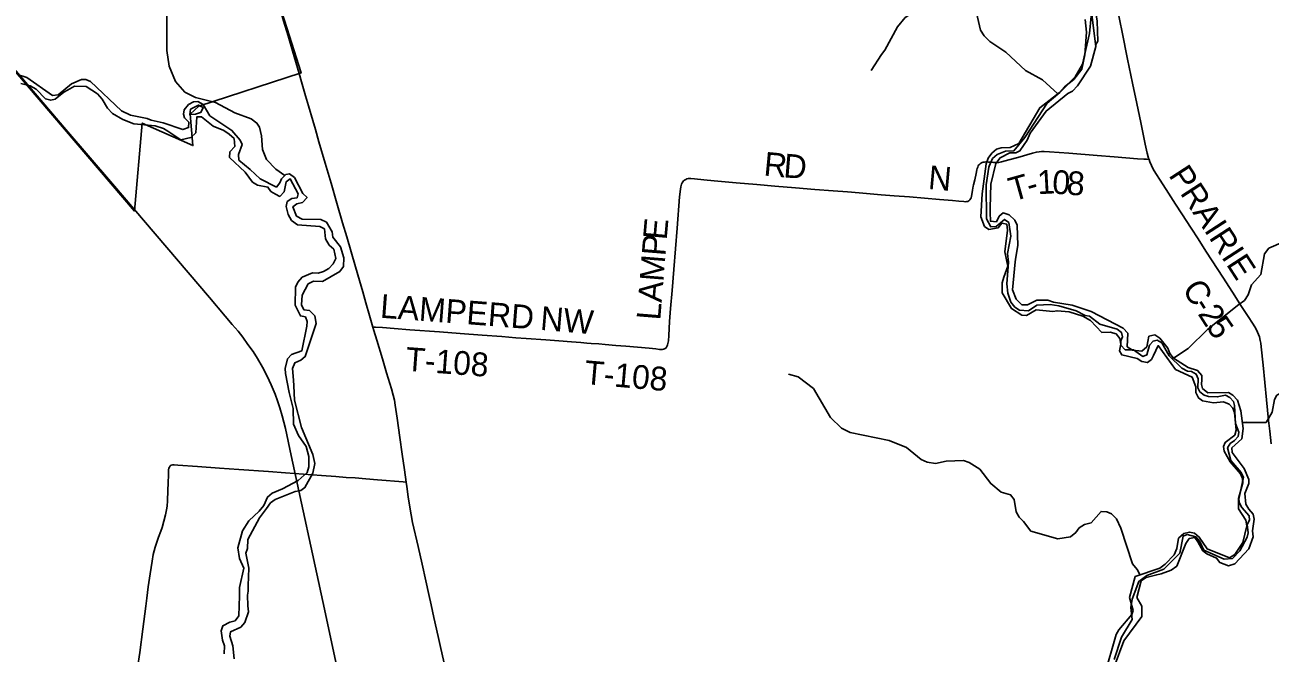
# Model space of a CAD drawing. Extents: x -51392 to 1635000, y 156707 to 696232.
# Drawn here: x 108334 to 124053, y 518358 to 526284 of the extents above; entities that cross this region are included whole.
import ezdxf

# ---------------------------------------------------------------- set-up
doc = ezdxf.new("R2010")
doc.units = 0
for name, color, linetype in [('GM_X_Corporation', 7, 'Continuous'), ('GM_X_County_Road', 7, 'Continuous'), ('GM_X_County_Road_Text', 7, 'Continuous'), ('GM_X_Major_River', 7, 'Continuous'), ('GM_X_Minor_River', 7, 'Continuous'), ('GM_X_Rail_Line', 7, 'Continuous'), ('GM_X_State_Route', 7, 'Continuous'), ('GM_X_Township', 7, 'Continuous'), ('GM_X_Township_Road', 7, 'Continuous'), ('GM_X_Township_Road_Text', 7, 'Continuous')]:
    doc.layers.add(name, color=color, linetype=linetype)

msp = doc.modelspace()

# ---------------------------------------------------------------- linework, layer by layer
at = {"layer": 'GM_X_Corporation'}
msp.add_lwpolyline([(111459, 526819), (111820, 525679), (110531, 525259), (110418, 525160), (110454, 524762), (109814, 525045), (109718, 523935), (107626, 526376)], dxfattribs=at)
at = {"layer": 'GM_X_County_Road'}
for points in [[(122525, 524588), (122520, 524603), (122502, 524666), (122476, 524778), (122420, 525051), (122370, 525292), (122317, 525549), (122253, 525854), (122185, 526192), (122156, 526337), (122110, 526561), (122091, 526658), (122068, 526770), (122045, 526883), (122009, 527060), (121987, 527155), (121961, 527250), (121922, 527375), (121848, 527610), (121792, 527781), (121760, 527874), (121738, 527924)], [(124067, 520997), (124049, 521160), (124035, 521291), (124009, 521552), (123964, 521992), (123942, 522221), (123936, 522270), (123930, 522302), (123919, 522349), (123908, 522379), (123895, 522409), (123872, 522452), (123838, 522508), (123767, 522618), (123686, 522742), (123607, 522866), (123464, 523087), (123242, 523431), (123145, 523583), (123055, 523721), (122940, 523900), (122860, 524023), (122771, 524161), (122664, 524326), (122611, 524409), (122577, 524466), (122555, 524510), (122536, 524556), (122525, 524588)], [(109757, 518171), (109785, 518365), (109823, 518658), (109860, 518951), (109872, 519049), (109891, 519195), (109914, 519357), (109926, 519438), (109939, 519519), (109954, 519600), (109965, 519648), (109978, 519696), (109999, 519758), (110021, 519820), (110050, 519897), (110066, 519943), (110088, 520022), (110108, 520101), (110121, 520165), (110128, 520213), (110133, 520278), (110138, 520409), (110141, 520508), (110145, 520606), (110146, 520655), (110148, 520672), (110151, 520689), (110157, 520705), (110167, 520720), (110182, 520730), (110199, 520735), (110216, 520735), (110265, 520731), (110511, 520712), (110789, 520693), (111034, 520676), (111410, 520649), (111623, 520633), (111737, 520625), (111851, 520615), (111966, 520606), (112080, 520599), (112260, 520584), (112391, 520575), (112505, 520567), (112636, 520556), (112783, 520544), (113110, 520519), (113146, 520516)]]:
    msp.add_lwpolyline(points, dxfattribs=at)
at = {"layer": 'GM_X_Major_River'}
for points in [[(121794, 522668), (121554, 522747), (121317, 522784), (121247, 522809), (121108, 522809), (120990, 522752), (120918, 522754), (120848, 522822), (120803, 522940), (120836, 523296), (120843, 523352), (120869, 523499), (120862, 523759), (120829, 523819), (120759, 523889), (120685, 523912), (120631, 523870), (120598, 523798), (120522, 523807), (120521, 523918), (120519, 523976), (120526, 524274), (120589, 524537), (120644, 524607), (120766, 524672), (120842, 524672), (120894, 524694), (120985, 524831), (121023, 524917), (121225, 525197), (121502, 525420), (121560, 525450), (121624, 525515), (121787, 525764), (121854, 526011), (121796, 526477)], [(121720, 526351), (121737, 526192), (121714, 525908), (121675, 525725), (121574, 525597), (121456, 525502), (121396, 525432), (121145, 525238), (120881, 524789), (120770, 524736), (120658, 524733), (120600, 524715), (120542, 524667), (120494, 524602), (120469, 524530), (120418, 524154), (120402, 523863), (120448, 523741), (120502, 523703), (120622, 523724), (120668, 523782), (120728, 523772), (120740, 523696), (120703, 523422), (120742, 523238), (120693, 523101), (120673, 523031), (120673, 522903), (120788, 522705), (120918, 522620), (120980, 522618), (121102, 522689), (121312, 522669), (121364, 522678), (121518, 522664), (121690, 522609), (121788, 522556)], [(110426, 525222), (110414, 525152), (110488, 525156), (110539, 525175)], [(110539, 525175), (110556, 525181), (110586, 525241), (110526, 525273), (110426, 525222)], [(121788, 522556), (121931, 522405), (122036, 522408), (122110, 522387), (122157, 522329), (122167, 522257), (122154, 522171), (122180, 522120), (122374, 522075), (122436, 522036), (122504, 522024), (122556, 522061), (122581, 522113), (122642, 522237), (122860, 521935), (123070, 521839), (123114, 521719), (123115, 521645), (123149, 521578), (123200, 521540), (123337, 521517), (123467, 521528), (123537, 521499), (123583, 521449), (123605, 521395), (123627, 521172), (123608, 521108), (123487, 521015), (123467, 520963), (123475, 520907), (123550, 520772), (123679, 520619), (123707, 520562), (123708, 520506), (123653, 520310), (123654, 520176), (123749, 520035), (123760, 519965), (123711, 519753), (123609, 519603), (123539, 519560), (123257, 519672), (123158, 519821), (123098, 519870), (123036, 519884), (122966, 519868), (122895, 519807), (122878, 519677), (122841, 519599), (122730, 519479), (122661, 519430), (122351, 519324), (122280, 519058)], [(122373, 519061), (122424, 519271), (122488, 519311), (122623, 519346), (122677, 519356), (122804, 519403), (122874, 519454), (122989, 519740), (123033, 519804), (123104, 519815), (123142, 519761), (123203, 519648), (123256, 519608), (123378, 519557), (123418, 519499), (123528, 519460), (123610, 519483), (123784, 519674), (123838, 519826), (123830, 519902), (123853, 520048), (123838, 520111), (123784, 520175), (123748, 520235), (123735, 520370), (123784, 520496), (123785, 520550), (123728, 520686), (123575, 520888), (123571, 520946), (123696, 521061), (123713, 521192), (123685, 521416), (123642, 521551), (123582, 521613), (123528, 521644), (123269, 521640), (123200, 521698), (123186, 521748), (123192, 521810), (123193, 521860), (123137, 521925), (123019, 521960), (122833, 522081), (122788, 522136), (122762, 522204), (122663, 522331), (122599, 522372), (122523, 522356), (122497, 522220), (122433, 522169), (122317, 522181), (122247, 522224), (122256, 522396), (122198, 522459), (121794, 522668)], [(122280, 519058), (122323, 518897), (122309, 518844), (122142, 518651), (122112, 518591), (121962, 518080)], [(122084, 518184), (122207, 518512), (122433, 518820), (122433, 518948), (122373, 519061)]]:
    msp.add_lwpolyline(points, dxfattribs=at)
at = {"layer": 'GM_X_Minor_River'}
for points in [[(121848, 526028), (121880, 526080), (121870, 526332), (121843, 526495), (121860, 526551), (121926, 526582), (122107, 526593), (122241, 526632), (122338, 526728), (122363, 526868), (122363, 527050), (122387, 527158), (122438, 527226), (122503, 527259), (122635, 527278), (122698, 527316), (122746, 527394), (122779, 527448), (122927, 527701)], [(109870, 527219), (109896, 527165), (109913, 526972), (110121, 526503), (110127, 526387), (110125, 525960), (110154, 525762), (110236, 525572), (110353, 525436), (110489, 525367), (110741, 525304), (110982, 525175), (111188, 525101), (111262, 525046), (111294, 524996), (111319, 524886), (111335, 524712), (111384, 524588), (111500, 524466), (111615, 524386)], [(121373, 525413), (121180, 525591), (120965, 525710), (120717, 525941), (120514, 526073), (120444, 526146), (120396, 526216), (120314, 526583), (120234, 526760), (120183, 526812), (120131, 526840), (120059, 526840), (119997, 526817), (119938, 526769), (119828, 526690), (119639, 526441), (119505, 526415), (119448, 526378), (119350, 526258), (119191, 525967), (119148, 525910), (119017, 525711)], [(111825, 522751), (111833, 522875), (111908, 523016), (111976, 523052), (112090, 523045), (112309, 523172), (112355, 523234), (112361, 523346), (112316, 523482), (112219, 523606), (112211, 523674), (112141, 523796), (112071, 523828), (111833, 523835), (111763, 523872), (111714, 523988), (111768, 524025), (111838, 524043), (111896, 524105), (111841, 524159), (111735, 524359), (111676, 524405), (111627, 524396), (111573, 524344), (111553, 524290), (111509, 524238), (111303, 524341), (111179, 524460), (111036, 524578), (111028, 524648), (111077, 524776), (111051, 524830), (110947, 524952), (110670, 525139), (110583, 525281), (110515, 525319), (110461, 525313), (110400, 525280), (110344, 525212), (110334, 525160), (110348, 525110), (110401, 525058), (110399, 524988), (110329, 524963), (110079, 525050), (109929, 525084), (109877, 525102), (109667, 525145), (109554, 525200), (109163, 525569), (109103, 525597), (109047, 525597), (108923, 525540), (108752, 525401), (108682, 525395), (108359, 525622), (108241, 525659)], [(108284, 525547), (108400, 525514), (108476, 525472), (108594, 525352), (108660, 525333), (108716, 525347), (108823, 525434), (108871, 525461), (108961, 525512), (109109, 525507), (109250, 525413), (109308, 525349), (109376, 525234), (109441, 525168), (109569, 525092), (109709, 525035), (109977, 525012), (110083, 524978), (110139, 524943), (110302, 524835), (110427, 524864), (110491, 524922), (110504, 525124), (110564, 525125), (110709, 525005), (110847, 524952), (110911, 524906), (110975, 524850), (110985, 524750), (110922, 524682), (110916, 524612), (111115, 524428), (111207, 524302), (111271, 524261), (111401, 524237), (111440, 524183), (111498, 524149), (111552, 524120), (111605, 524176), (111633, 524306), (111683, 524341), (111783, 524153), (111770, 524103), (111702, 524092), (111644, 524054), (111630, 523992), (111659, 523890), (111701, 523818), (111775, 523762), (112055, 523741), (112115, 523710), (112130, 523586), (112174, 523506), (112232, 523454), (112257, 523336), (112227, 523271), (112169, 523211), (112103, 523171), (112036, 523150), (111964, 523154), (111834, 523101), (111778, 523037), (111750, 522973), (111745, 522749), (111812, 522613), (111874, 522599), (111898, 522541), (111894, 522481), (111830, 522172), (111698, 522126), (111650, 522069), (111619, 521949), (111623, 521885), (111668, 521645), (111719, 521445), (111726, 521248), (111786, 521104), (111883, 520965), (111919, 520837), (111920, 520708), (111898, 520636), (111785, 520536), (111587, 520429), (111455, 520376), (111396, 520326), (111348, 520219), (111290, 520149), (111159, 520026), (111082, 519900), (111023, 519685), (111041, 519551), (111096, 519431), (111041, 519184), (111044, 519081)], [(110426, 525222), (110414, 525152), (110488, 525156), (110539, 525175)], [(110539, 525175), (110556, 525181), (110586, 525241), (110526, 525273), (110426, 525222)], [(122833, 522081), (123017, 522202), (123267, 522447), (123657, 522755), (123729, 522808), (123776, 522880), (123817, 523006), (123936, 523133), (123982, 523396), (124039, 523467), (124224, 523548)], [(111145, 519087), (111151, 519137), (111152, 519211), (111160, 519429), (111121, 519619), (111145, 519676), (111148, 519790), (111297, 520063), (111382, 520183), (111432, 520252), (111492, 520296), (111747, 520395), (111815, 520408), (111869, 520446), (111970, 520629), (111994, 520751), (111967, 520863), (111826, 521205), (111738, 521549), (111728, 521731), (111723, 521801), (111713, 521949), (111740, 522020), (111818, 522054), (111872, 522100), (112010, 522515), (111992, 522614), (111926, 522679), (111856, 522691), (111825, 522751)], [(123703, 521266), (123820, 521267), (124003, 521266), (124078, 521397), (124109, 521559), (124138, 521611), (124192, 521643), (124326, 521650), (124537, 521608), (124655, 521634), (124720, 521679), (124766, 521739), (124830, 521923)], [(121793, 520002), (121711, 519979), (121643, 519937), (121603, 519881), (121534, 519826), (121374, 519800), (121034, 519896), (120939, 520020), (120885, 520074), (120849, 520140), (120822, 520294), (120778, 520356), (120658, 520387), (120526, 520497), (120387, 520678), (120255, 520762), (120182, 520788), (119965, 520781), (119831, 520752), (119723, 520766), (119649, 520801), (119462, 520953), (119244, 521040), (118752, 521142), (118642, 521197), (118503, 521329), (118362, 521575), (118288, 521696), (118097, 521844), (117973, 521879)], [(123758, 521279), (123758, 521279)], [(122407, 519351), (122374, 519412), (122317, 519482), (122170, 519936), (122116, 520051), (122051, 520116), (121991, 520142), (121919, 520145), (121793, 520002)], [(111044, 519081), (111036, 518828), (110987, 518763), (110919, 518747), (110832, 518702), (110812, 518640), (110827, 518519), (110853, 518451), (110850, 518347)], [(110976, 518284), (110959, 518448), (110922, 518573), (110928, 518625), (111059, 518686), (111112, 518742), (111155, 518880), (111149, 518956), (111145, 519087)]]:
    msp.add_lwpolyline(points, dxfattribs=at)
at = {"layer": 'GM_X_Rail_Line'}
msp.add_lwpolyline([(112518, 517028), (112093, 519008), (111697, 520852), (111624, 521192), (111582, 521353), (111553, 521454), (111524, 521539), (111493, 521626), (111444, 521744), (111393, 521854), (111335, 521964), (111271, 522073), (111216, 522163), (111150, 522253), (111083, 522345), (111025, 522419), (110952, 522504), (110863, 522610), (110663, 522844), (109438, 524277), (108852, 524964), (107807, 526186)], dxfattribs=at)
at = {"layer": 'GM_X_State_Route'}
for points in [[(111795, 525670), (111711, 525958), (111656, 526147), (111600, 526336), (111541, 526542), (111533, 526568)], [(113628, 518231), (113576, 518455), (113551, 518567), (113497, 518807), (113462, 518967), (113433, 519095), (113393, 519271), (113347, 519479), (113297, 519704), (113228, 520007), (113208, 520104), (113191, 520200), (113171, 520330), (113154, 520460), (113146, 520516), (113124, 520671), (113098, 520866), (113068, 521078), (113034, 521321), (113010, 521484), (112998, 521548), (112983, 521612), (112962, 521692), (112899, 521896), (112847, 522069), (112778, 522305), (112740, 522430), (112728, 522471), (112684, 522619), (112639, 522777), (112598, 522918), (112557, 523060), (112506, 523233), (112396, 523611), (112345, 523785), (112271, 524037), (112199, 524289), (112126, 524541), (112046, 524808), (112001, 524966), (111968, 525076), (111914, 525265), (111877, 525391), (111827, 525564), (111795, 525670)]]:
    msp.add_lwpolyline(points, dxfattribs=at)
at = {"layer": 'GM_X_Township'}
for points in [[(121793, 526396), (121774, 526177), (121683, 525788), (121594, 525631), (121400, 525433), (121237, 525295), (120956, 524862), (120819, 524697), (120714, 524692), (120607, 524649), (120547, 524597), (120507, 524503), (120502, 524490), (120467, 524267), (120475, 523836), (120528, 523735), (120596, 523741), (120701, 523830), (120756, 523790), (120781, 523618), (120739, 523399), (120752, 523289), (120730, 523018), (120741, 522900), (120782, 522784), (120832, 522721), (120891, 522685), (121005, 522676), (121108, 522749), (121277, 522756), (121387, 522741), (121606, 522678), (121718, 522617), (121772, 522608), (121904, 522508), (122121, 522446), (122176, 522404), (122188, 522350), (122168, 522296), (122170, 522244), (122222, 522186), (122327, 522184), (122445, 522102), (122499, 522122), (122531, 522242), (122577, 522295), (122628, 522305), (122686, 522271), (122781, 522110), (122939, 521954), (123010, 521916), (123062, 521910), (123120, 521878), (123144, 521818), (123139, 521706), (123167, 521656), (123221, 521614), (123275, 521596), (123386, 521590), (123492, 521612), (123544, 521584), (123591, 521532), (123603, 521480), (123617, 521254), (123660, 521146), (123650, 521092), (123602, 521039), (123549, 521001), (123517, 520947), (123558, 520789), (123689, 520637), (123717, 520579), (123659, 520298), (123669, 520248), (123695, 520194), (123790, 520090), (123792, 520036), (123766, 519980), (123778, 519874), (123766, 519821), (123670, 519649), (123578, 519551), (123474, 519541), (123216, 519655), (123168, 519767), (123114, 519823), (123005, 519855), (122955, 519833), (122913, 519618), (122711, 519418), (122498, 519337), (122396, 519261), (122313, 519040), (122296, 518934), (122314, 518783), (122178, 518559), (122084, 518275)], [(122084, 518275), (122178, 518559), (122314, 518783), (122296, 518934), (122313, 519040), (122396, 519261), (122498, 519337), (122711, 519418), (122913, 519618), (122955, 519833), (123005, 519855), (123114, 519823), (123168, 519767), (123216, 519655), (123474, 519541), (123578, 519551), (123670, 519649), (123766, 519821), (123778, 519874), (123766, 519980), (123792, 520036), (123790, 520090), (123695, 520194), (123669, 520248), (123659, 520298), (123717, 520579), (123689, 520637), (123558, 520789), (123517, 520947), (123549, 521001), (123602, 521039), (123650, 521092), (123660, 521146), (123617, 521254), (123603, 521480), (123591, 521532), (123544, 521584), (123492, 521612), (123386, 521590), (123275, 521596), (123221, 521614), (123167, 521656), (123139, 521706), (123144, 521818), (123120, 521878), (123062, 521910), (123010, 521916), (122939, 521954), (122781, 522110), (122686, 522271), (122628, 522305), (122577, 522295), (122531, 522242), (122499, 522122), (122445, 522102), (122327, 522184), (122222, 522186), (122170, 522244), (122168, 522296), (122188, 522350), (122176, 522404), (122121, 522446), (121904, 522508), (121772, 522608), (121718, 522617), (121606, 522678), (121387, 522741), (121277, 522756), (121108, 522749), (121005, 522676), (120891, 522685), (120832, 522721), (120782, 522784), (120741, 522900), (120730, 523018), (120752, 523289), (120739, 523399), (120781, 523618), (120756, 523790), (120701, 523830), (120596, 523741), (120528, 523735), (120475, 523836), (120467, 524267), (120502, 524490), (120507, 524503), (120547, 524597), (120607, 524649), (120714, 524692), (120819, 524697), (120956, 524862), (121237, 525295), (121400, 525433), (121594, 525631), (121683, 525788), (121774, 526177), (121793, 526396)]]:
    msp.add_lwpolyline(points, dxfattribs=at)
at = {"layer": 'GM_X_Township_Road'}
for points in [[(120531, 524551), (120563, 524548), (120596, 524547), (120628, 524550), (120661, 524556), (120756, 524580), (120867, 524611), (121055, 524667), (121103, 524679), (121136, 524683), (121168, 524686), (121201, 524686), (121267, 524683), (121512, 524666), (121872, 524635), (122084, 524618), (122378, 524594), (122460, 524589), (122493, 524589), (122525, 524588)], [(115428, 522270), (115481, 522265), (115579, 522258), (115661, 522251), (115792, 522241), (115922, 522230), (116069, 522218), (116216, 522204), (116298, 522195), (116347, 522188), (116363, 522187), (116380, 522188), (116396, 522191), (116410, 522198), (116423, 522207), (116434, 522219), (116442, 522233), (116448, 522248), (116452, 522264), (116457, 522297), (116462, 522363), (116473, 522543), (116485, 522706), (116503, 522935), (116524, 523197), (116567, 523720), (116598, 524113), (116608, 524211), (116614, 524243), (116618, 524259), (116624, 524275), (116631, 524290), (116639, 524303), (116650, 524316), (116662, 524326), (116676, 524335), (116691, 524341), (116706, 524345), (116723, 524347), (116739, 524347), (116788, 524343), (116903, 524329), (117033, 524316), (117311, 524292), (117573, 524271), (117802, 524251), (118063, 524230), (118308, 524208), (118537, 524190), (118717, 524176), (118864, 524166), (119142, 524141), (119306, 524128), (119502, 524113), (119878, 524083), (120042, 524067), (120123, 524060), (120189, 524054), (120205, 524053), (120222, 524054), (120238, 524057), (120252, 524064), (120264, 524075), (120272, 524089), (120278, 524104), (120282, 524120), (120297, 524201), (120306, 524249), (120310, 524265), (120324, 524329), (120343, 524409), (120353, 524457), (120357, 524473), (120362, 524489), (120369, 524504), (120378, 524517), (120389, 524529), (120402, 524539), (120417, 524546), (120432, 524551), (120448, 524554), (120465, 524555), (120498, 524554), (120531, 524551)], [(112728, 522471), (112758, 522469), (112848, 522464), (112996, 522454), (113191, 522438), (113567, 522411), (113829, 522391), (114107, 522369), (114353, 522351), (114533, 522337), (114663, 522328), (114909, 522310), (115072, 522298), (115236, 522287), (115350, 522277), (115428, 522270)]]:
    msp.add_lwpolyline(points, dxfattribs=at)

# ---------------------------------------------------------------- texts
at = {"layer": 'GM_X_County_Road_Text'}
for s, rotation, p in [('PRAIRIE', 302.9154, (122765, 524388)), ('C', 302.1877, (122936, 522954)), ('2', 302.6727, (123134, 522639)), ('-', 302.2926, (123067, 522745)), ('5', 303.9891, (123238, 522477))]:
    msp.add_text(s, height=300, rotation=rotation, dxfattribs=at).set_placement(p)
at = {"layer": 'GM_X_Township_Road_Text'}
for s, rotation, p in [('R', 354.6113, (117653, 524385)), ('D', 355.3195, (117903, 524362)), ('N', 354.8269, (119729, 524215)), ('1', 3.1413, (121121, 524147)), ('0', 356.0848, (121296, 524157)), ('8', 356.0584, (121480, 524144)), ('T', 15.6444, (120803, 524055)), ('-', 15.748, (121020, 524116)), ('E', 84.9499, (116435, 523564)), ('P', 85.4, (116419, 523362)), ('M', 85.4215, (116393, 523038)), ('A', 85.421, (116372, 522775)), ('LAMPE', 355.7249, (112812, 522590)), ('RD', 355.5502, (114171, 522488)), ('NW', 355.1553, (114832, 522437)), ('L', 85.4233, (116354, 522551)), ('T-108', 355.7748, (113131, 521921)), ('T-108', 354.9931, (115388, 521754))]:
    msp.add_text(s, height=300, rotation=rotation, dxfattribs=at).set_placement(p)

doc.saveas('drawing.dxf')
